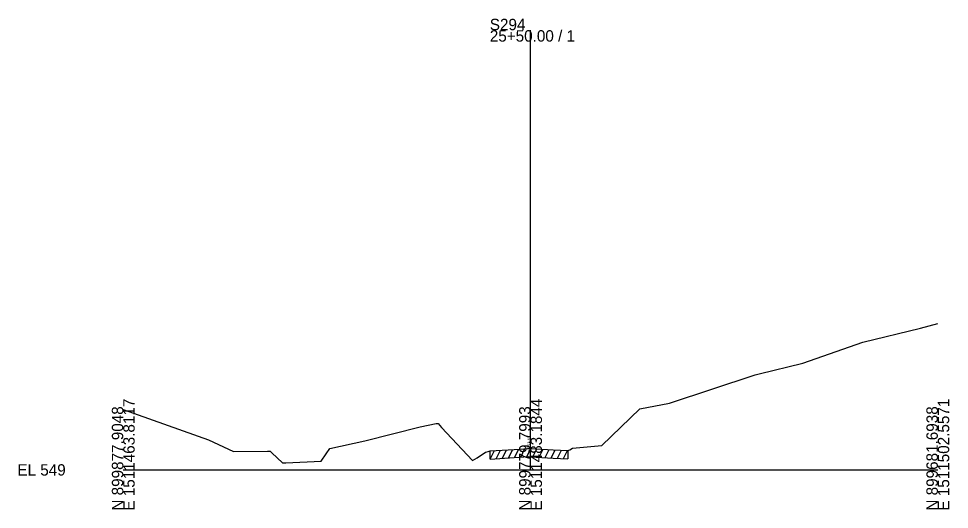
# Model space of a CAD drawing. Extents: x 974 to 2203, y -10 to 19041.
# Drawn here: x 1974.3 to 2202.8, y 10990.3 to 11110.8 of the extents above; entities that cross this region are included whole.
import ezdxf

# ---------------------------------------------------------------- set-up
doc = ezdxf.new("R2010")
doc.units = 0
for name, color, linetype in [('RD_GPK_XS_Cell', 7, 'Continuous'), ('RD_XS_ExGround', 7, 'Continuous'), ('RD_XS_ExPaveRet', 7, 'Continuous'), ('RD_XS_TX_Elev_EX', 7, 'Continuous')]:
    doc.layers.add(name, color=color, linetype=linetype)

msp = doc.modelspace()

# ---------------------------------------------------------------- linework, layer by layer
at = {"layer": 'RD_GPK_XS_Cell'}
for p, q in [((2100, 11000), (2100, 11107.92)), ((2000, 11000), (2100, 11000)), ((2100, 11000), (2200, 11000))]:
    msp.add_line(p, q, dxfattribs=at)
at = {"layer": 'RD_XS_ExGround'}
msp.add_lwpolyline([(2000, 11014.8), (2020.89, 11007.35), (2027.1, 11004.48), (2035.45, 11004.59), (2036.06, 11004.58), (2036.44, 11004.22), (2039.06, 11001.75), (2039.95, 11001.7), (2048.6, 11002.14), (2049.79, 11003.97), (2050.69, 11005.21), (2059.33, 11007.15), (2072.92, 11010.53), (2076.79, 11011.38), (2077.34, 11011.36), (2078.11, 11010.38), (2085.79, 11002.32), (2086.9, 11002.95), (2088.95, 11004.39), (2089.58, 11004.52), (2090.09, 11004.65), (2095.97, 11005.04), (2099.58, 11005.27), (2100, 11005.24), (2105.56, 11004.91), (2109.17, 11004.73), (2109.65, 11004.94), (2110.32, 11005.33), (2117.51, 11006.02), (2126.81, 11015.02), (2134.1, 11016.36), (2155.12, 11023.34), (2156.16, 11023.59), (2166.87, 11026.22), (2181.57, 11031.37), (2195.75, 11034.78), (2200, 11035.97)], dxfattribs=at)
at = {"layer": 'RD_XS_ExPaveRet'}
for p, q in [((2090.09, 11002.65), (2091.13, 11004.72)), ((2090.09, 11002.65), (2090.09, 11004.65)), ((2091.59, 11002.75), (2092.63, 11004.82)), ((2093.09, 11002.85), (2094.13, 11004.92)), ((2094.59, 11002.95), (2095.63, 11005.02)), ((2096.09, 11003.05), (2097.13, 11005.11)), ((2097.59, 11003.14), (2098.63, 11005.21)), ((2099.09, 11003.24), (2100.09, 11005.24)), ((2100.59, 11003.21), (2101.56, 11005.15)), ((2102.09, 11003.12), (2103.06, 11005.06)), ((2103.59, 11003.03), (2104.56, 11004.97)), ((2105.09, 11002.94), (2106.07, 11004.88)), ((2106.59, 11002.86), (2107.57, 11004.81)), ((2108.09, 11002.78), (2109.07, 11004.73)), ((2109.17, 11004.73), (2109.17, 11002.73)), ((2090.09, 11002.65), (2095.97, 11003.04)), ((2095.97, 11003.04), (2099.58, 11003.27)), ((2099.58, 11003.27), (2100, 11003.24)), ((2100, 11003.24), (2105.56, 11002.91)), ((2105.56, 11002.91), (2109.17, 11002.73))]:
    msp.add_line(p, q, dxfattribs=at)

# ---------------------------------------------------------------- texts
at = {"layer": 'RD_GPK_XS_Cell'}
for s, p in [('S294', (2090, 11107.92)), ('25+50.00 / 1', (2090, 11105.12)), ('EL 549', (1974, 10998.6))]:
    msp.add_text(s, height=2.8, dxfattribs=at).set_placement(p)
for s, p in [('N 899877.9048', (2000, 10990)), ('E 1511463.8117', (2002.8, 10990)), ('N 899779.7993', (2100, 10990)), ('E 1511483.1844', (2102.8, 10990)), ('N 899681.6938', (2200, 10990)), ('E 1511502.5571', (2202.8, 10990))]:
    msp.add_text(s, height=2.8, rotation=90, dxfattribs=at).set_placement(p)
at = {"layer": 'RD_XS_TX_Elev_EX'}
msp.add_text('551.62', height=0.75, rotation=90, dxfattribs=at).set_placement((2100, 11005.24))

doc.saveas('drawing.dxf')
